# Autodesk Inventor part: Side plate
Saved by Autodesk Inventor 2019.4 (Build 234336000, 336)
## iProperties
Created: 2020-04
Part Number: Side plate
Material: Generic
Document SubType Name: Modeling
Designer: Administrator
Density: 1 g/cm^3
Appearance: Default
Title: Side plate v3
Author: Administrator
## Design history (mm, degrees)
feature "Body1"
body "Solid1"
